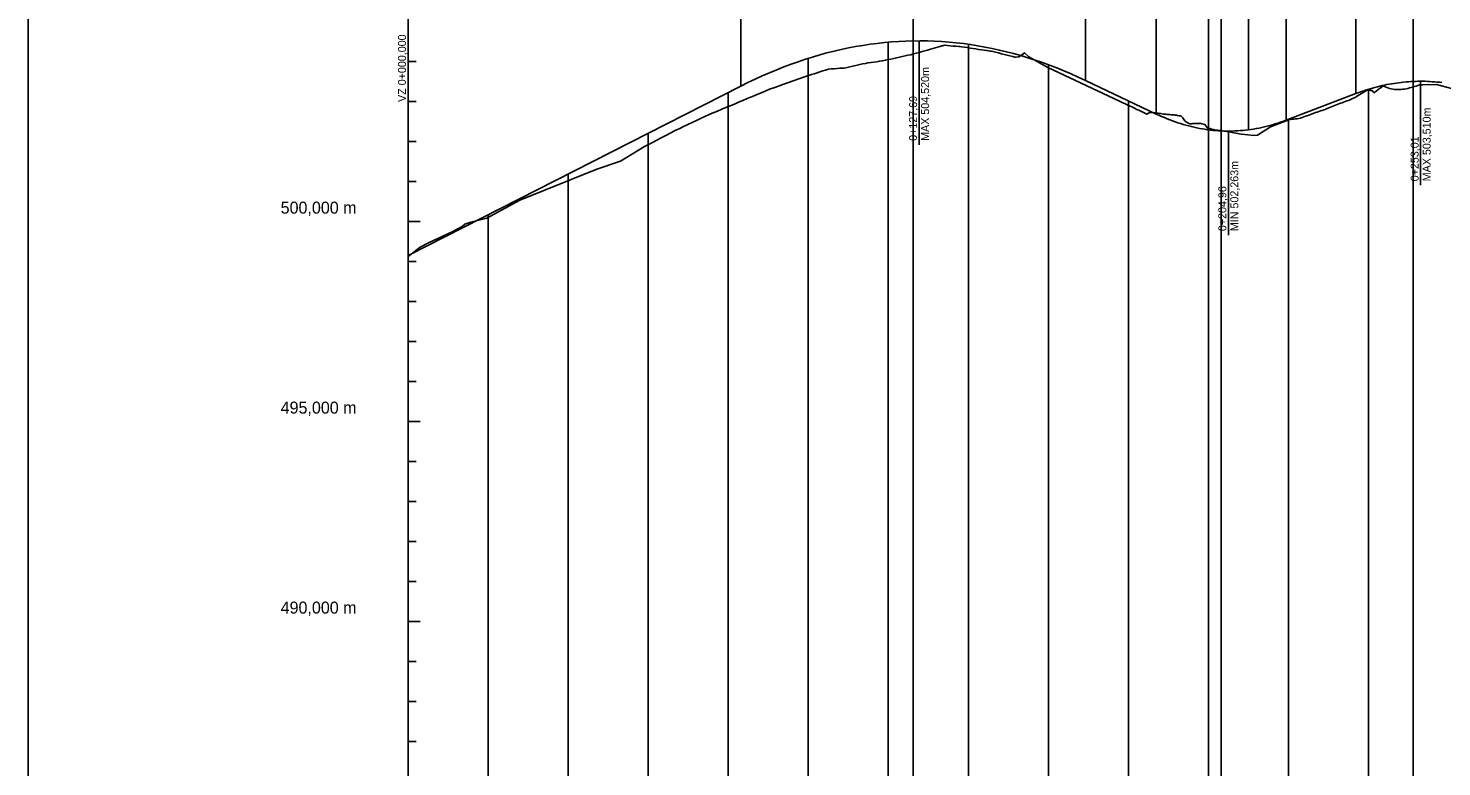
# Model space of a CAD drawing. Extents: x -632716 to -629545, y -1094726 to -1088285.
# Drawn here: x -632546.8 to -632193.7, y -1090191.9 to -1090007.3 of the extents above; entities that cross this region are included whole.
import ezdxf

# ---------------------------------------------------------------- set-up
doc = ezdxf.new("R2010")
doc.units = 0
for name, color, linetype in [('20', 7, 'Continuous'), ('Default', 7, 'Continuous'), ('formát', 7, 'Continuous'), ('REZ_POPIS', 7, 'Continuous'), ('REZ_TENKA', 7, 'Continuous'), ('REZ_TLUSTA', 7, 'Continuous'), ('SKLONY_NIVELETA', 7, 'Continuous'), ('SKLONY_POPIS', 7, 'Continuous'), ('TECNY_NIVELETA', 7, 'Continuous'), ('VOZOVKA', 7, 'Continuous')]:
    doc.layers.add(name, color=color, linetype=linetype)

msp = doc.modelspace()

# ---------------------------------------------------------------- linework, layer by layer
at = {"layer": '20'}
for points in [[(-632331.95, -1090010.76), (-632331.95, -1090205.62), (-632331.95, -1090255.62), (-632331.95, -1090195.62)], [(-632311.95, -1090011.29), (-632311.95, -1090205.62), (-632311.95, -1090255.62), (-632311.95, -1090195.62)], [(-632351.95, -1090014.81), (-632351.95, -1090205.62), (-632351.95, -1090255.62), (-632351.95, -1090195.62)], [(-632291.95, -1090016.39), (-632291.95, -1090205.62), (-632291.95, -1090255.62), (-632291.95, -1090195.62)], [(-632211.95, -1090022.52), (-632211.95, -1090205.62), (-632211.95, -1090255.62), (-632211.95, -1090195.62)], [(-632371.95, -1090023.37), (-632371.95, -1090205.62), (-632371.95, -1090255.62), (-632371.95, -1090195.62)], [(-632271.95, -1090025.4), (-632271.95, -1090205.62), (-632271.95, -1090255.62), (-632271.95, -1090195.62)], [(-632231.95, -1090030.01), (-632231.95, -1090205.62), (-632231.95, -1090255.62), (-632231.95, -1090195.62)], [(-632391.95, -1090033.55), (-632391.95, -1090205.62), (-632391.95, -1090255.62), (-632391.95, -1090195.62)], [(-632251.95, -1090032.66), (-632251.95, -1090205.62), (-632251.95, -1090255.62), (-632251.95, -1090195.62)], [(-632411.95, -1090043.74), (-632411.95, -1090205.62), (-632411.95, -1090255.62), (-632411.95, -1090195.62)], [(-632431.95, -1090053.92), (-632431.95, -1090205.62), (-632431.95, -1090255.62), (-632431.95, -1090195.62)], [(-632451.95, -1090064.11), (-632451.95, -1090205.62), (-632451.95, -1090255.62), (-632451.95, -1090195.62)]]:
    msp.add_lwpolyline(points, dxfattribs=at)
at = {"layer": 'Default'}
for p, q in [((-632451.95, -1090064.11), (-632368.81, -1090021.77)), ((-632282.69, -1090020.3), (-632265, -1090028.71)), ((-632232.58, -1090030.24), (-632215.14, -1090023.61))]:
    msp.add_line(p, q, dxfattribs=at)
for points in [[(-632368.81, -1090021.77), (-632367.02, -1090020.87), (-632365.23, -1090020.01), (-632363.43, -1090019.19), (-632361.64, -1090018.41), (-632359.84, -1090017.66), (-632358.05, -1090016.95), (-632356.26, -1090016.27), (-632354.46, -1090015.64), (-632352.67, -1090015.03), (-632350.87, -1090014.47), (-632349.08, -1090013.94), (-632347.28, -1090013.45), (-632345.49, -1090013), (-632343.7, -1090012.58), (-632341.9, -1090012.2), (-632340.11, -1090011.86), (-632338.31, -1090011.55), (-632336.52, -1090011.28), (-632334.72, -1090011.05), (-632332.93, -1090010.85), (-632331.14, -1090010.69), (-632329.34, -1090010.57), (-632327.55, -1090010.48), (-632323.96, -1090010.42), (-632322.16, -1090010.45), (-632320.37, -1090010.51), (-632318.58, -1090010.61), (-632316.78, -1090010.74), (-632314.99, -1090010.91), (-632313.19, -1090011.12), (-632311.4, -1090011.37), (-632309.61, -1090011.65), (-632307.81, -1090011.97), (-632306.02, -1090012.33), (-632304.22, -1090012.72), (-632302.43, -1090013.15), (-632300.63, -1090013.61), (-632298.84, -1090014.12), (-632297.05, -1090014.66), (-632295.25, -1090015.23), (-632293.46, -1090015.85), (-632291.66, -1090016.5), (-632289.87, -1090017.18), (-632288.07, -1090017.91), (-632286.28, -1090018.67), (-632284.49, -1090019.47), (-632282.69, -1090020.3)], [(-632215.14, -1090023.61), (-632214.54, -1090023.39), (-632213.94, -1090023.17), (-632213.35, -1090022.96), (-632212.75, -1090022.77), (-632212.15, -1090022.58), (-632211.56, -1090022.4), (-632210.96, -1090022.22), (-632210.36, -1090022.06), (-632209.76, -1090021.9), (-632209.17, -1090021.76), (-632208.57, -1090021.62), (-632207.97, -1090021.49), (-632207.38, -1090021.36), (-632206.78, -1090021.25), (-632206.18, -1090021.14), (-632205.59, -1090021.05), (-632204.99, -1090020.96), (-632204.39, -1090020.88), (-632203.8, -1090020.8), (-632203.2, -1090020.74), (-632202.6, -1090020.68), (-632202.01, -1090020.64), (-632201.41, -1090020.6), (-632200.22, -1090020.55), (-632199.62, -1090020.53), (-632199.02, -1090020.53), (-632198.43, -1090020.53), (-632197.83, -1090020.54), (-632197.23, -1090020.56), (-632196.64, -1090020.59), (-632196.04, -1090020.63), (-632195.44, -1090020.67), (-632194.85, -1090020.72), (-632194.25, -1090020.78), (-632193.65, -1090020.85)], [(-632265, -1090028.71), (-632264.32, -1090029.02), (-632263.65, -1090029.33), (-632262.97, -1090029.62), (-632262.29, -1090029.9), (-632261.62, -1090030.16), (-632260.94, -1090030.42), (-632260.27, -1090030.66), (-632259.59, -1090030.89), (-632258.92, -1090031.11), (-632258.24, -1090031.32), (-632257.57, -1090031.51), (-632256.89, -1090031.69), (-632256.22, -1090031.86), (-632255.54, -1090032.02), (-632254.87, -1090032.17), (-632254.19, -1090032.3), (-632253.51, -1090032.43), (-632252.84, -1090032.54), (-632252.16, -1090032.63), (-632251.49, -1090032.72), (-632250.81, -1090032.8), (-632250.14, -1090032.86), (-632249.46, -1090032.91), (-632248.11, -1090032.97), (-632247.44, -1090032.99), (-632246.76, -1090032.99), (-632246.08, -1090032.98), (-632245.41, -1090032.95), (-632244.73, -1090032.92), (-632244.06, -1090032.87), (-632243.38, -1090032.82), (-632242.71, -1090032.75), (-632242.03, -1090032.66), (-632241.36, -1090032.57), (-632240.68, -1090032.46), (-632240.01, -1090032.34), (-632239.33, -1090032.21), (-632238.65, -1090032.07), (-632237.98, -1090031.92), (-632237.3, -1090031.75), (-632236.63, -1090031.57), (-632235.95, -1090031.38), (-632235.28, -1090031.18), (-632234.6, -1090030.96), (-632233.93, -1090030.73), (-632233.25, -1090030.5), (-632232.58, -1090030.24)]]:
    msp.add_lwpolyline(points, dxfattribs=at)
at = {"layer": 'formát'}
msp.add_lwpolyline([(-632546.83, -1090378.9), (-629545.24, -1090378.9), (-629545.24, -1089784.9), (-632546.83, -1089784.9)], close=True, dxfattribs=at)
at = {"layer": 'REZ_TENKA'}
for p, q in [((-632451.95, -1090255.62), (-632451.95, -1089955.62)), ((-632451.95, -1090015.62), (-632449.95, -1090015.62)), ((-632451.95, -1090025.62), (-632449.95, -1090025.62)), ((-632451.95, -1090035.62), (-632449.95, -1090035.62)), ((-632451.95, -1090045.62), (-632449.95, -1090045.62)), ((-632451.95, -1090065.62), (-632449.95, -1090065.62)), ((-632451.95, -1090075.62), (-632449.95, -1090075.62)), ((-632451.95, -1090085.62), (-632449.95, -1090085.62)), ((-632451.95, -1090095.62), (-632449.95, -1090095.62)), ((-632451.95, -1090115.62), (-632449.95, -1090115.62)), ((-632451.95, -1090125.62), (-632449.95, -1090125.62)), ((-632451.95, -1090135.62), (-632449.95, -1090135.62)), ((-632451.95, -1090145.62), (-632449.95, -1090145.62)), ((-632451.95, -1090165.62), (-632449.95, -1090165.62)), ((-632451.95, -1090175.62), (-632449.95, -1090175.62)), ((-632451.95, -1090185.62), (-632449.95, -1090185.62))]:
    msp.add_line(p, q, dxfattribs=at)
at = {"layer": 'REZ_TLUSTA'}
for p, q in [((-632451.95, -1090055.62), (-632448.95, -1090055.62)), ((-632451.95, -1090105.62), (-632448.95, -1090105.62)), ((-632451.95, -1090155.62), (-632448.95, -1090155.62))]:
    msp.add_line(p, q, dxfattribs=at)
at = {"layer": 'SKLONY_NIVELETA'}
for p, q in [((-632241.95, -1089873.26), (-632241.95, -1090032.65)), ((-632325.75, -1089899.84), (-632325.75, -1090255.62)), ((-632200.81, -1089918.16), (-632200.81, -1090255.62)), ((-632248.79, -1089936.41), (-632248.79, -1090255.62)), ((-632451.95, -1090064.11), (-632368.81, -1090021.77)), ((-632282.69, -1090020.3), (-632265, -1090028.71)), ((-632232.58, -1090030.24), (-632215.14, -1090023.61))]:
    msp.add_line(p, q, dxfattribs=at)
for points in [[(-632368.81, -1090021.77), (-632367.02, -1090020.87), (-632365.23, -1090020.01), (-632363.43, -1090019.19), (-632361.64, -1090018.41), (-632359.84, -1090017.66), (-632358.05, -1090016.95), (-632356.26, -1090016.27), (-632354.46, -1090015.64), (-632352.67, -1090015.03), (-632350.87, -1090014.47), (-632349.08, -1090013.94), (-632347.28, -1090013.45), (-632345.49, -1090013), (-632343.7, -1090012.58), (-632341.9, -1090012.2), (-632340.11, -1090011.86), (-632338.31, -1090011.55), (-632336.52, -1090011.28), (-632334.72, -1090011.05), (-632332.93, -1090010.85), (-632331.14, -1090010.69), (-632329.34, -1090010.57), (-632327.55, -1090010.48), (-632323.96, -1090010.42), (-632322.16, -1090010.45), (-632320.37, -1090010.51), (-632318.58, -1090010.61), (-632316.78, -1090010.74), (-632314.99, -1090010.91), (-632313.19, -1090011.12), (-632311.4, -1090011.37), (-632309.61, -1090011.65), (-632307.81, -1090011.97), (-632306.02, -1090012.33), (-632304.22, -1090012.72), (-632302.43, -1090013.15), (-632300.63, -1090013.61), (-632298.84, -1090014.12), (-632297.05, -1090014.66), (-632295.25, -1090015.23), (-632293.46, -1090015.85), (-632291.66, -1090016.5), (-632289.87, -1090017.18), (-632288.07, -1090017.91), (-632286.28, -1090018.67), (-632284.49, -1090019.47), (-632282.69, -1090020.3)], [(-632215.14, -1090023.61), (-632214.54, -1090023.39), (-632213.94, -1090023.17), (-632213.35, -1090022.96), (-632212.75, -1090022.77), (-632212.15, -1090022.58), (-632211.56, -1090022.4), (-632210.96, -1090022.22), (-632210.36, -1090022.06), (-632209.76, -1090021.9), (-632209.17, -1090021.76), (-632208.57, -1090021.62), (-632207.97, -1090021.49), (-632207.38, -1090021.36), (-632206.78, -1090021.25), (-632206.18, -1090021.14), (-632205.59, -1090021.05), (-632204.99, -1090020.96), (-632204.39, -1090020.88), (-632203.8, -1090020.8), (-632203.2, -1090020.74), (-632202.6, -1090020.68), (-632202.01, -1090020.64), (-632201.41, -1090020.6), (-632200.22, -1090020.55), (-632199.62, -1090020.53), (-632199.02, -1090020.53), (-632198.43, -1090020.53), (-632197.83, -1090020.54), (-632197.23, -1090020.56), (-632196.64, -1090020.59), (-632196.04, -1090020.63), (-632195.44, -1090020.67), (-632194.85, -1090020.72), (-632194.25, -1090020.78), (-632193.65, -1090020.85)], [(-632265, -1090028.71), (-632264.32, -1090029.02), (-632263.65, -1090029.33), (-632262.97, -1090029.62), (-632262.29, -1090029.9), (-632261.62, -1090030.16), (-632260.94, -1090030.42), (-632260.27, -1090030.66), (-632259.59, -1090030.89), (-632258.92, -1090031.11), (-632258.24, -1090031.32), (-632257.57, -1090031.51), (-632256.89, -1090031.69), (-632256.22, -1090031.86), (-632255.54, -1090032.02), (-632254.87, -1090032.17), (-632254.19, -1090032.3), (-632253.51, -1090032.43), (-632252.84, -1090032.54), (-632252.16, -1090032.63), (-632251.49, -1090032.72), (-632250.81, -1090032.8), (-632250.14, -1090032.86), (-632249.46, -1090032.91), (-632248.11, -1090032.97), (-632247.44, -1090032.99), (-632246.76, -1090032.99), (-632246.08, -1090032.98), (-632245.41, -1090032.95), (-632244.73, -1090032.92), (-632244.06, -1090032.87), (-632243.38, -1090032.82), (-632242.71, -1090032.75), (-632242.03, -1090032.66), (-632241.36, -1090032.57), (-632240.68, -1090032.46), (-632240.01, -1090032.34), (-632239.33, -1090032.21), (-632238.65, -1090032.07), (-632237.98, -1090031.92), (-632237.3, -1090031.75), (-632236.63, -1090031.57), (-632235.95, -1090031.38), (-632235.28, -1090031.18), (-632234.6, -1090030.96), (-632233.93, -1090030.73), (-632233.25, -1090030.5), (-632232.58, -1090030.24)]]:
    msp.add_lwpolyline(points, dxfattribs=at)
at = {"layer": 'TECNY_NIVELETA'}
for p, q in [((-632241.95, -1090032.65), (-632241.95, -1089839.22)), ((-632251.95, -1090032.66), (-632251.95, -1089863.77)), ((-632282.69, -1090020.3), (-632282.69, -1089919.3)), ((-632368.81, -1090021.77), (-632368.81, -1089920.77)), ((-632215.14, -1090023.61), (-632215.14, -1089922.61)), ((-632265, -1090028.71), (-632265, -1089927.71)), ((-632232.58, -1090030.24), (-632232.58, -1089929.24)), ((-632324.26, -1090010.42), (-632324.26, -1090036.42)), ((-632198.94, -1090020.53), (-632198.94, -1090046.53)), ((-632246.99, -1090032.99), (-632246.99, -1090058.99))]:
    msp.add_line(p, q, dxfattribs=at)
at = {"layer": 'VOZOVKA'}
msp.add_lwpolyline([(-632451.95, -1090064.31), (-632450.4, -1090063.16), (-632448.95, -1090062.03), (-632446.85, -1090060.89), (-632440.89, -1090058.16), (-632438.42, -1090056.83), (-632437.73, -1090056.23), (-632436.23, -1090055.72), (-632432.28, -1090054.76), (-632424.03, -1090050.24), (-632404.8, -1090042.51), (-632398.87, -1090040.49), (-632392.85, -1090036.87), (-632392.01, -1090036.43), (-632390.9, -1090035.84), (-632389.79, -1090035.26), (-632388.68, -1090034.67), (-632387.57, -1090034.08), (-632386.46, -1090033.5), (-632385.35, -1090032.91), (-632385.27, -1090032.87), (-632384.23, -1090032.39), (-632383.12, -1090031.87), (-632382.01, -1090031.35), (-632380.96, -1090030.85), (-632379.9, -1090030.35), (-632378.85, -1090029.86), (-632377.79, -1090029.36), (-632376.74, -1090028.86), (-632376.39, -1090028.7), (-632375.68, -1090028.41), (-632374.63, -1090027.97), (-632373.57, -1090027.53), (-632372.52, -1090027.09), (-632371.46, -1090026.65), (-632370.41, -1090026.21), (-632369.35, -1090025.77), (-632368.3, -1090025.34), (-632367.19, -1090024.87), (-632366.35, -1090024.53), (-632366.07, -1090024.41), (-632364.96, -1090023.94), (-632363.85, -1090023.47), (-632362.74, -1090023.01), (-632361.63, -1090022.54), (-632361.39, -1090022.44), (-632360.52, -1090022.13), (-632359.41, -1090021.73), (-632358.3, -1090021.33), (-632352.87, -1090019.39), (-632352.6, -1090019.3), (-632351.88, -1090019.08), (-632351.17, -1090018.85), (-632350.46, -1090018.63), (-632349.74, -1090018.4), (-632349.03, -1090018.18), (-632348.31, -1090017.95), (-632347.6, -1090017.73), (-632346.88, -1090017.5), (-632346.81, -1090017.48), (-632346.17, -1090017.43), (-632345.46, -1090017.38), (-632344.74, -1090017.34), (-632344.03, -1090017.29), (-632343.31, -1090017.26), (-632343.05, -1090017.24), (-632342.6, -1090017.14), (-632341.89, -1090016.97), (-632341.19, -1090016.81), (-632340.48, -1090016.65), (-632339.77, -1090016.5), (-632339.07, -1090016.34), (-632338.36, -1090016.19), (-632337.66, -1090016.05), (-632337.04, -1090015.92), (-632336.95, -1090015.91), (-632336.24, -1090015.82), (-632335.54, -1090015.72), (-632334.83, -1090015.63), (-632334.13, -1090015.54), (-632334.11, -1090015.54), (-632333.42, -1090015.4), (-632332.71, -1090015.26), (-632332.01, -1090015.11), (-632331.3, -1090014.96), (-632330.59, -1090014.81), (-632329.89, -1090014.66), (-632329.18, -1090014.51), (-632328.48, -1090014.36), (-632327.77, -1090014.2), (-632327.06, -1090014.04), (-632326.36, -1090013.89), (-632326.14, -1090013.84), (-632325.65, -1090013.7), (-632324.95, -1090013.51), (-632324.24, -1090013.31), (-632323.53, -1090013.12), (-632322.83, -1090012.92), (-632322.12, -1090012.72), (-632321.41, -1090012.52), (-632320.71, -1090012.31), (-632320, -1090012.11), (-632319.3, -1090011.9), (-632318.59, -1090011.7), (-632318.44, -1090011.65), (-632317.88, -1090011.54), (-632317.88, -1090011.54), (-632317.18, -1090011.6), (-632316.47, -1090011.65), (-632315.77, -1090011.71), (-632315.06, -1090011.76), (-632314.35, -1090011.81), (-632314.09, -1090011.83), (-632313.65, -1090011.9), (-632312.94, -1090012.01), (-632312.23, -1090012.12), (-632311.53, -1090012.23), (-632310.82, -1090012.34), (-632310.12, -1090012.44), (-632309.41, -1090012.55), (-632308.7, -1090012.65), (-632307.99, -1090012.76), (-632307.42, -1090012.84), (-632307.28, -1090012.86), (-632306.56, -1090012.96), (-632306.14, -1090013.02), (-632305.85, -1090013.09), (-632305.13, -1090013.27), (-632304.42, -1090013.45), (-632303.7, -1090013.63), (-632302.99, -1090013.82), (-632302.28, -1090014), (-632301.56, -1090014.18), (-632300.85, -1090014.37), (-632300.39, -1090014.49), (-632300.13, -1090014.47), (-632299.47, -1090014.43), (-632299.42, -1090014.43), (-632299.36, -1090014.44), (-632298.7, -1090013.98), (-632297.9, -1090013.43), (-632296.8, -1090014.38), (-632292.12, -1090017.1), (-632274.18, -1090025.5), (-632273.86, -1090025.65), (-632273.53, -1090025.81), (-632273.21, -1090025.96), (-632272.89, -1090026.11), (-632272.57, -1090026.26), (-632272.24, -1090026.41), (-632271.92, -1090026.56), (-632271.6, -1090026.71), (-632271.28, -1090026.87), (-632270.95, -1090027.02), (-632270.63, -1090027.17), (-632270.31, -1090027.32), (-632269.98, -1090027.48), (-632269.66, -1090027.63), (-632269.34, -1090027.78), (-632269.02, -1090027.94), (-632268.69, -1090028.09), (-632268.37, -1090028.24), (-632268.05, -1090028.4), (-632267.73, -1090028.55), (-632267.4, -1090028.71), (-632267.33, -1090028.74), (-632267.08, -1090028.6), (-632266.76, -1090028.4), (-632266.61, -1090028.31), (-632266.44, -1090028.33), (-632266.11, -1090028.36), (-632265.79, -1090028.39), (-632265.47, -1090028.43), (-632265.15, -1090028.46), (-632264.82, -1090028.5), (-632264.5, -1090028.54), (-632264.18, -1090028.58), (-632263.86, -1090028.62), (-632263.54, -1090028.66), (-632263.21, -1090028.71), (-632262.92, -1090028.75), (-632262.89, -1090028.75), (-632262.57, -1090028.77), (-632262.25, -1090028.8), (-632261.93, -1090028.83), (-632261.61, -1090028.86), (-632261.29, -1090028.89), (-632260.97, -1090028.92), (-632260.65, -1090028.95), (-632260.32, -1090028.99), (-632260, -1090029.03), (-632259.94, -1090029.04), (-632259.68, -1090029.08), (-632259.36, -1090029.13), (-632259.04, -1090029.19), (-632258.78, -1090029.23), (-632258.72, -1090029.3), (-632258.4, -1090029.69), (-632258.08, -1090030.08), (-632257.75, -1090030.48), (-632257.67, -1090030.58), (-632257.43, -1090030.72), (-632257.11, -1090030.9), (-632256.79, -1090031.07), (-632256.64, -1090031.15), (-632256.47, -1090031.15), (-632256.15, -1090031.13), (-632255.83, -1090031.12), (-632255.51, -1090031.1), (-632255.18, -1090031.09), (-632254.86, -1090031.08), (-632254.54, -1090031.06), (-632254.22, -1090031.05), (-632254.04, -1090031.04), (-632253.9, -1090031.08), (-632253.58, -1090031.16), (-632253.26, -1090031.24), (-632252.94, -1090031.32), (-632252.83, -1090031.35), (-632252.62, -1090031.66), (-632252.29, -1090032.11), (-632252.22, -1090032.22), (-632251.97, -1090032.29), (-632251.65, -1090032.37), (-632251.33, -1090032.45), (-632251.01, -1090032.53), (-632250.68, -1090032.61), (-632250.59, -1090032.63), (-632250.34, -1090032.67), (-632250.01, -1090032.71), (-632249.68, -1090032.76), (-632249.34, -1090032.81), (-632249.01, -1090032.85), (-632248.68, -1090032.9), (-632248.34, -1090032.95), (-632248.01, -1090032.99), (-632247.68, -1090033.04), (-632247.34, -1090033.08), (-632247.01, -1090033.13), (-632246.68, -1090033.18), (-632246.67, -1090033.18), (-632246.34, -1090033.24), (-632246.01, -1090033.3), (-632243.67, -1090033.75), (-632240.56, -1090034.11), (-632239.74, -1090034.04), (-632236.45, -1090031.89), (-632231.89, -1090030.14), (-632231.85, -1090030.13), (-632231.43, -1090030.08), (-632231.02, -1090030.03), (-632230.6, -1090029.98), (-632230.18, -1090029.93), (-632229.77, -1090029.88), (-632229.35, -1090029.83), (-632228.99, -1090029.79), (-632228.93, -1090029.76), (-632228.52, -1090029.6), (-632228.1, -1090029.44), (-632227.68, -1090029.28), (-632227.27, -1090029.13), (-632226.85, -1090028.97), (-632226.43, -1090028.82), (-632226.02, -1090028.66), (-632225.6, -1090028.51), (-632225.18, -1090028.37), (-632224.77, -1090028.22), (-632224.35, -1090028.08), (-632223.93, -1090027.94), (-632223.52, -1090027.81), (-632223.1, -1090027.67), (-632222.83, -1090027.59), (-632222.68, -1090027.52), (-632222.46, -1090027.42), (-632222.27, -1090027.34), (-632221.85, -1090027.17), (-632221.44, -1090027), (-632221.04, -1090026.83), (-632220.63, -1090026.67), (-632220.22, -1090026.51), (-632219.81, -1090026.35), (-632219.41, -1090026.19), (-632219, -1090026.04), (-632218.59, -1090025.88), (-632218.19, -1090025.74), (-632217.78, -1090025.59), (-632217.37, -1090025.45), (-632216.97, -1090025.31), (-632216.74, -1090025.23), (-632216.56, -1090025.15), (-632216.15, -1090024.95), (-632215.74, -1090024.76), (-632215.34, -1090024.58), (-632215.06, -1090024.45), (-632214.93, -1090024.36), (-632214.52, -1090024.1), (-632214.12, -1090023.84), (-632213.71, -1090023.59), (-632213.3, -1090023.34), (-632212.9, -1090023.09), (-632212.49, -1090022.84), (-632212.32, -1090022.75), (-632212.08, -1090022.76), (-632211.67, -1090022.78), (-632211.42, -1090022.8), (-632211.27, -1090022.83), (-632211.04, -1090022.87), (-632210.86, -1090023.05), (-632210.5, -1090023.4), (-632210.45, -1090023.36), (-632210.05, -1090023.02), (-632209.64, -1090022.69), (-632209.23, -1090022.37), (-632208.82, -1090022.05), (-632208.42, -1090021.74), (-632208.33, -1090021.67), (-632208, -1090021.84), (-632207.58, -1090022.02), (-632207.17, -1090022.18), (-632206.75, -1090022.31), (-632206.33, -1090022.41), (-632205.92, -1090022.49), (-632205.5, -1090022.55), (-632205.08, -1090022.58), (-632204.67, -1090022.59), (-632204.25, -1090022.58), (-632203.83, -1090022.56), (-632203.42, -1090022.52), (-632203, -1090022.46), (-632202.58, -1090022.39), (-632202.17, -1090022.3), (-632201.75, -1090022.2), (-632201.33, -1090022.1), (-632200.92, -1090021.98), (-632200.5, -1090021.86), (-632200.08, -1090021.73), (-632199.67, -1090021.59), (-632199.25, -1090021.45), (-632199.14, -1090021.42), (-632198.83, -1090021.41), (-632198.42, -1090021.4), (-632195.01, -1090021.3), (-632171.26, -1090027.68)], dxfattribs=at)

# ---------------------------------------------------------------- texts
at = {"layer": 'REZ_POPIS'}
for s, p in [('500,000 m', (-632483.77, -1090053.62)), ('495,000 m', (-632483.77, -1090103.62)), ('490,000 m', (-632483.77, -1090153.62))]:
    msp.add_text(s, height=3, dxfattribs=at).set_placement(p)
at = {"layer": 'SKLONY_POPIS'}
for s, p in [('VZ 0+000,000', (-632452.45, -1090025.69)), ('MAX 504,520m', (-632321.76, -1090035.42)), ('0+127,69', (-632324.76, -1090035.42)), ('MAX 503,510m', (-632196.44, -1090045.53)), ('0+253,01', (-632199.44, -1090045.53)), ('MIN 502,263m', (-632244.49, -1090057.99)), ('0+204,96', (-632247.49, -1090057.99))]:
    msp.add_text(s, height=2, rotation=90, dxfattribs=at).set_placement(p)

doc.saveas('drawing.dxf')
